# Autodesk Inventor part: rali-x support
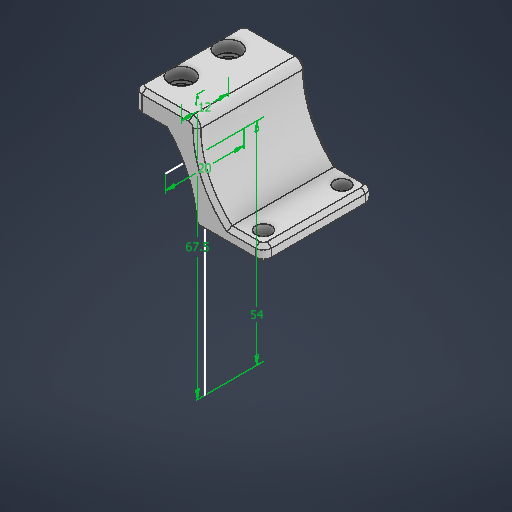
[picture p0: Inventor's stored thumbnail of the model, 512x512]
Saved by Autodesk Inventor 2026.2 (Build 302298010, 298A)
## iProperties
Created: 2026-04
Part Number: rali-x support
Material: 일반
Document SubType Name: Modeling
Designer: work
Density: 1 g/cm^3
Appearance: 기본값
Author: work
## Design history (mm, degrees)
sketch "스케치1"
  geometry: L1 (0, 0)-(67.5, 0); L2 (54, 10)-(54, -10); L3 (67.5, 6)-(67.5, -6); 1 further point
  constraints: 6 end point, 2 midpoint, 2 vertical, 1 horizontal, 1 point on line
  dimensions: "d0" = 67.5 distance of L1.start L1.end; "d1" = 54 distance of L1.start point (54, 0); "d2" = 20 distance of L2.start L2.end; "d3" = 12 distance of L3.start L3.end
node "작업 평면1"
sketch "스케치2"
  geometry: L1 (0, 6)-(0, -6); L2 (4, 10)-(-12, 10); L3 (-12, 10)-(-12, -10); L4 (-12, -10)-(4, -10); L5 (4, -10)-(4, 10); L6 (4, 14)-(-12, 14); L7 (-12, 14)-(-12, -14); L8 (-12, -14)-(4, -14); L9 (4, -14)-(4, 14); C1 r 2 at (0, 6); C2 r 2 at (0, -6); 8 further points
  constraints: 18 end point, 6 midpoint, 4 parallel, 2 centre point, 2 coincident, 2 horizontal, 2 perpendicular, 1 vertical
  dimensions: "d5" = 12 distance of L1.start L1.end; "d6" = 4 diameter of C1; "d7" = 4 diameter of C2; "d8" = 4 horizontal distance of point (-4, 10) L1.start; "d9" = 4 distance from line of L4 L1.end; "d10" = 4 distance from line of L5 L1.end; "d11" = 12 distance from line of L3 L1.end; "d26" = 28 distance between parallel lines of L8 L6
extrude "돌출1" new body sketch "스케치2" distance "d12" = 6; taper "d13" = 0 deg
node "작업 평면2"
sketch "스케치3"
  geometry: L1 (0, 0)-(-25, 0); L2 (-25, 10)-(-25, -10); L3 (-29, 14)-(-21, 14); L4 (-21, 14)-(-21, -14); L5 (-21, -14)-(-29, -14); L6 (-29, -14)-(-29, 14); L7 (-29, 14)-(-21, -14); L8 (-21, 14)-(-29, -14); L9 (-21, 14)-(-11, 14); L10 (-11, 14)-(-11, -14); L11 (-11, -14)-(-21, -14); L12 (-21, -14)-(-21, 14); C1 r 2 at (-25, 10); C2 r 2 at (-25, -10); 1 further point
  constraints: 24 end point, 4 midpoint, 4 parallel, 3 horizontal, 2 centre point, 2 coincident, 2 perpendicular, 1 point on line, 1 vertical
  dimensions: "d15" = 20 distance of L2.start L2.end; "d16" = 25 distance of L1.start L1.end; "d17" = 4 diameter of C1; "d18" = 4 diameter of C2; "d19" = 4 distance from line of L4 L2.end; "d20" = 4 distance of point (-25, -14) L2.end; "d23" = 10 distance between parallel lines of L4 L10
extrude "돌출2" join sketch "스케치3" distance "d21" = 4; taper "d22" = 0 deg
sketch "스케치5"
  geometry: L1 (18, -4)-(0, -4) reference; L2 (1, 13.5)-(-15, 13.5) reference; L3 (0, 0)-(0, -4) reference; L4 (-15, 13.5)-(1, 13.5) reference; L5 (1, 13.5)-(1, 17.5) reference; L6 (-15, 17.5)-(1, 17.5) reference; L7 (-15, 13.5)-(-15, 17.5) reference; L8 (0, 0)-(18, 0) reference; L9 (0, 0)-(0, -4) reference; L10 (18, -4)-(0, -4) reference; L11 (18, 0)-(18, -4) reference; L12 (-7, 13.5)-(-7, 17.5); L13 (9, 0)-(9, -4); A1 r 25.375 centre (-25.375, -4) between (0, -4) and (-7, 13.5); A2 r 23.141 centre (24.141, 17.5) between (1, 17.5) and (9, 0); 3 further points
  constraints: 4 end point, 4 midpoint, 4 point on circle, 2 centre point, 2 tangent, 1 perpendicular
extrude "돌출3" join sketch "스케치5" stored distance "d24" = 12 (= d3); taper "d25" = 0 deg
fillet "모깎기1" dims "d27" = 2
chamfer "모따기1" distance "d28" = 1; stored, may be unused: second distance "d29" = 2, angle "d30" = 45 deg
sketch "스케치6"
  geometry: L1 (-2, 13)-(10, 13) reference; L2 (-3, -12)-(-3, 12) reference; L3 (10, -13)-(-2, -13) reference; L4 (10, 13)-(10, -13) reference; C1 r 2 at (0, 6) reference; C2 r 2 at (0, -6) reference; A1 r 1 centre (-2, 12) between (-2, 13) and (-3, 12) reference; A2 r 1 centre (-2, -12) between (-3, -12) and (-2, -13) reference; 3 further points
  constraints: 2 coincident
hole "구멍1" sketch "스케치6" at (0, 6), (0, -6) diameter "d31" = 4; stored, may be unused: countersink angle "d35" = 90 deg, drill point angle "d37" = 118 deg; dims "d32" = 6, "d33" = 6.2, "d34" = 3, "d36" = 8
node "솔리드1"
node "투영된 루프3"
node "투영된 루프4"
node "투영된 루프5"
feature "A9D066F2-1C7D-4E18-AEED-F7BC21143FA4" dims "d31" = 4, "d32" = 6, "d33" = 6.2, "d34" = 3, "d35" = 90 deg, "d36" = 8, "d37" = 118 deg
other parameters: "d4" = 67.5, "d14" = 54
